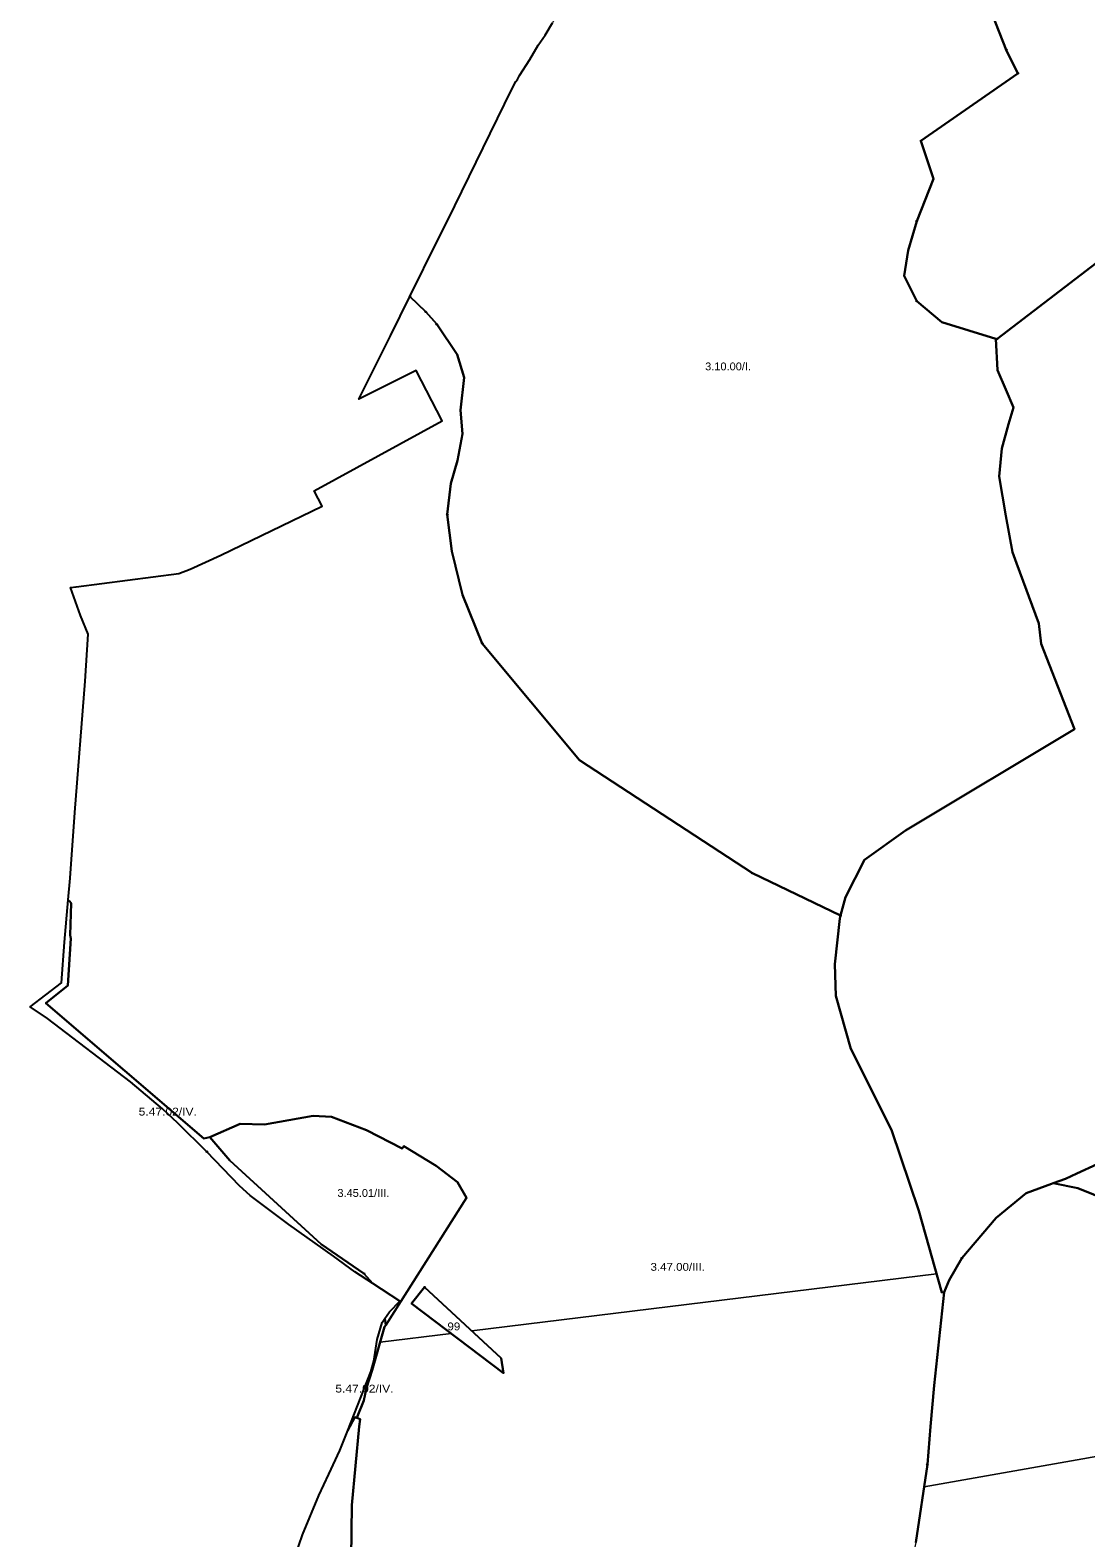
# Model space of a CAD drawing. Extents: x -650455 to -642254, y -1075222 to -1066610.
# Drawn here: x -649036 to -647687, y -1073142 to -1071216 of the extents above; entities that cross this region are included whole.
import ezdxf
from ezdxf.enums import TextEntityAlignment as Align

# ---------------------------------------------------------------- set-up
doc = ezdxf.new("R2010")
doc.units = 0
doc.header["$LTSCALE"] = 4
doc.header["$PDMODE"] = 32
doc.header["$PDSIZE"] = 2
for name, color, linetype, lineweight in [('1', 7, 'Continuous', 25), ('11', 7, 'Continuous', 13), ('12', 7, 'Continuous', 13), ('13', 7, 'Continuous', 13), ('14', 7, 'Continuous', 13), ('16', 7, 'Continuous', 13)]:
    doc.layers.add(name, color=color, linetype=linetype, lineweight=lineweight)
doc.layers.add('2', color=7, linetype='Continuous')

msp = doc.modelspace()

# ---------------------------------------------------------------- linework, layer by layer
at = {"layer": '1'}
for points in [[(-647994, -1072324), (-648000.504, -1072347.414), (-648113.117, -1072293.193), (-648334.004, -1072148.767), (-648458.304, -1071999.711), (-648483.733, -1071937.503), (-648497.128, -1071881.651), (-648503.031, -1071835.108), (-648498.263, -1071795.376), (-648489.863, -1071765.861), (-648483.733, -1071731.805), (-648486, -1071701.501), (-648481.5, -1071660), (-648490.5, -1071630.501), (-648516.5, -1071592), (-648530.5, -1071576.001), (-648550.69, -1071556.284), (-648515.528, -1071484.719), (-648502.316, -1071458.869), (-648421.035, -1071292.285), (-648415.434, -1071281.946), (-648413.28, -1071279.36), (-648410.551, -1071274.192), (-648397.483, -1071253.511), (-648386.713, -1071235.418), (-648378.097, -1071222.492), (-648368.619, -1071206.983)], [(-647806.937, -1071195.687), (-647788.736, -1071241.189), (-647773.924, -1071271.486), (-647897.806, -1071357.665), (-647881.648, -1071406.14), (-647903.192, -1071460.002), (-647913.965, -1071497.705), (-647919.351, -1071530.022), (-647903.192, -1071562.339), (-647870.875, -1071589.27), (-647801.949, -1071610.478), (-647799.782, -1071650.366), (-647789.455, -1071675.321), (-647779.56, -1071698.124), (-647786.013, -1071719.637), (-647794.619, -1071750.616), (-647797.63, -1071786.328), (-647789.455, -1071836.453), (-647780.85, -1071882.921), (-647775.687, -1071897.12), (-647747.29, -1071974.351), (-647744.278, -1072000.167), (-647701.628, -1072109.378), (-647917.5, -1072238.5), (-647970, -1072276), (-647994, -1072324)], [(-647412.981, -1071489.088), (-647446.149, -1071408.082), (-647470.706, -1071328.032), (-647494.813, -1071270.777), (-647498.258, -1071279.39), (-647499.23, -1071276.872), (-647515.389, -1071314.575), (-647547.706, -1071336.12), (-647526.161, -1071400.754), (-647800.855, -1071610.814), (-647801.949, -1071610.478), (-647870.875, -1071589.27), (-647903.192, -1071562.339), (-647919.351, -1071530.022), (-647913.965, -1071497.705), (-647903.192, -1071460.002), (-647881.648, -1071406.14), (-647897.806, -1071357.665), (-647773.924, -1071271.486), (-647788.736, -1071241.189), (-647806.937, -1071195.687)], [(-647672.5, -1072665), (-647698.521, -1072676.851), (-647713.137, -1072683.505), (-647728.952, -1072689.256), (-647731, -1072690.001), (-647763.5, -1072702.001), (-647801.5, -1072733.5), (-647845.5, -1072785), (-647861.5, -1072813), (-647868, -1072828.501), (-647871, -1072829.001), (-647900.5, -1072724.5), (-647935.5, -1072621.001), (-647987.5, -1072517.5), (-648006.5, -1072450), (-648008, -1072409.5), (-648001.5, -1072351.001), (-648000.504, -1072347.414), (-647994, -1072324), (-647970, -1072276), (-647917.5, -1072238.5), (-647701.628, -1072109.378), (-647744.278, -1072000.167), (-647747.29, -1071974.351), (-647775.687, -1071897.12), (-647780.85, -1071882.921), (-647789.455, -1071836.453), (-647797.63, -1071786.328), (-647794.619, -1071750.616), (-647786.013, -1071719.637), (-647779.56, -1071698.124), (-647789.455, -1071675.321), (-647799.782, -1071650.366), (-647801.949, -1071610.478), (-647800.855, -1071610.814), (-647526.161, -1071400.754)], [(-648845.916, -1071910.237), (-648831.479, -1071904.954), (-648792.396, -1071886.988), (-648662.822, -1071824.472), (-648673.033, -1071804.745), (-648509.304, -1071715.273), (-648542.754, -1071651.164), (-648615.992, -1071687.445), (-648575.5, -1071606.779), (-648550.69, -1071556.284), (-648530.5, -1071576.001), (-648516.5, -1071592), (-648490.5, -1071630.501)], [(-648490.5, -1071630.501), (-648481.5, -1071660), (-648486, -1071701.501), (-648483.733, -1071731.805), (-648489.863, -1071765.861), (-648498.263, -1071795.376), (-648503.031, -1071835.108), (-648497.128, -1071881.651), (-648483.733, -1071937.503), (-648458.304, -1071999.711), (-648334.004, -1072148.767), (-648113.117, -1072293.193), (-648000.504, -1072347.414), (-648001.5, -1072351.001), (-648008, -1072409.5), (-648006.5, -1072450), (-647987.5, -1072517.5), (-647935.5, -1072621.001), (-647900.5, -1072724.5), (-647871, -1072829.001), (-647868, -1072828.501), (-647881, -1072947.5), (-647885.418, -1073000), (-647889.5, -1073048.5), (-647904.5, -1073148.001)], [(-648626.5, -1073235.5), (-648625, -1073100.5), (-648615.407, -1073000), (-648614.5, -1072990.501), (-648618.5, -1072989), (-648609.5, -1072967), (-648606, -1072950.5), (-648599, -1072928), (-648583, -1072872.501), (-648581.642, -1072870.363), (-648478.5, -1072708), (-648490, -1072688), (-648517, -1072667.001), (-648558.691, -1072641.986), (-648560.5, -1072645.001), (-648606, -1072621.501), (-648651, -1072604.501), (-648674.5, -1072603), (-648736.5, -1072614.001), (-648767.5, -1072613.501), (-648806.5, -1072630.501), (-648814, -1072632), (-649016, -1072459.001), (-648988, -1072436.5), (-648984, -1072376.5), (-648985, -1072372.5), (-648983.5, -1072331.5), (-648985.611, -1072329.098), (-648987.292, -1072327.185), (-648984.907, -1072299.389), (-648978.921, -1072215.554), (-648965.541, -1072047.881), (-648961.667, -1071987.999), (-648971.526, -1071964.046), (-648984.389, -1071928.3), (-648977.161, -1071927.325), (-648845.916, -1071910.237)], [(-647639.5, -1072719.001), (-647697.5, -1072695.5), (-647728.952, -1072689.256), (-647713.137, -1072683.505), (-647698.521, -1072676.851), (-647672.5, -1072665), (-647660, -1072659.5), (-647610, -1072633.501), (-647571.5, -1072606.001), (-647536, -1072573.001), (-647511.5, -1072543), (-647500, -1072504.667), (-647498, -1072498), (-647495, -1072475.501), (-647474.5, -1072442.501), (-647439.5, -1072402.001), (-647391, -1072357), (-647361, -1072335.5), (-647349, -1072333), (-647336.5, -1072335.5), (-647316, -1072351.5), (-647308, -1072361.501)], [(-647904.5, -1073148.001), (-647889.5, -1073048.5), (-647885.418, -1073000), (-647881, -1072947.5), (-647868, -1072828.501), (-647861.5, -1072813), (-647845.5, -1072785), (-647801.5, -1072733.5), (-647763.5, -1072702.001), (-647731, -1072690.001), (-647728.952, -1072689.256), (-647697.5, -1072695.5), (-647639.5, -1072719.001), (-647587, -1072756.001), (-647543, -1072805.5), (-647522, -1072821.5), (-647515.5, -1072825), (-647500, -1072834.548), (-647453, -1072863.5), (-647421.34, -1072872.531), (-647410, -1072877.001), (-647339.5, -1072889.001)], [(-648697.333, -1073165.774), (-648687.999, -1073138.202), (-648667.032, -1073088.227), (-648654.486, -1073060.948), (-648640.322, -1073030.783), (-648630.2, -1073005.113), (-648627.452, -1073000), (-648621, -1072988), (-648618.5, -1072989), (-648614.5, -1072990.501), (-648615.407, -1073000), (-648625, -1073100.5), (-648626.5, -1073235.5)]]:
    msp.add_lwpolyline(points, dxfattribs=at)
for points in [[(-649016, -1072459.001), (-648814, -1072632), (-648806.5, -1072630.501), (-648781, -1072660), (-648664, -1072767.001), (-648609.5, -1072804.501), (-648598.112, -1072817.407), (-648620.935, -1072802.594), (-648648.364, -1072782.202), (-648705.519, -1072741.992), (-648754.776, -1072704.94), (-648768.275, -1072692.734), (-648810.208, -1072648.934), (-648847.402, -1072612.314), (-648866.789, -1072594.363), (-648907.86, -1072559.755), (-649013.849, -1072478.813), (-649035.963, -1072463.892), (-648995.823, -1072433.245), (-648991.95, -1072381.465), (-648987.292, -1072327.185), (-648985.611, -1072329.098), (-648983.5, -1072331.5), (-648985, -1072372.5), (-648984, -1072376.5), (-648988, -1072436.5)], [(-648581.642, -1072870.363), (-648582.835, -1072862.192), (-648576.781, -1072853.444), (-648563.753, -1072839.708), (-648598.112, -1072817.407), (-648609.5, -1072804.501), (-648664, -1072767.001), (-648781, -1072660), (-648806.5, -1072630.501), (-648767.5, -1072613.501), (-648736.5, -1072614.001), (-648674.5, -1072603), (-648651, -1072604.501), (-648606, -1072621.501), (-648560.5, -1072645.001), (-648558.691, -1072641.986), (-648517, -1072667.001), (-648490, -1072688), (-648478.5, -1072708)], [(-648434, -1072912.501), (-648431, -1072932), (-648548.5, -1072843), (-648532, -1072822)], [(-648548.5, -1072843), (-648431, -1072932), (-648434, -1072912.501), (-648532, -1072822)], [(-648609.5, -1072967), (-648618.5, -1072989), (-648621, -1072988), (-648627.452, -1073000), (-648630.2, -1073005.113), (-648600.686, -1072930.26), (-648596.665, -1072916.474), (-648592.501, -1072888.9), (-648586.288, -1072867.182), (-648582.835, -1072862.192), (-648581.642, -1072870.363), (-648583, -1072872.501), (-648599, -1072928), (-648606, -1072950.5)]]:
    msp.add_lwpolyline(points, close=True, dxfattribs=at)
at = {"layer": '11'}
msp.add_line((-647788.736, -1071241.189), (-647806.937, -1071195.687), dxfattribs=at)
for points in [[(-648327.713, -1071139.525), (-648367.47, -1071204.399), (-648368.619, -1071206.983), (-648378.097, -1071222.492), (-648386.713, -1071235.418), (-648397.483, -1071253.511), (-648410.551, -1071274.192), (-648413.28, -1071279.36), (-648415.434, -1071281.946), (-648421.035, -1071292.285), (-648502.316, -1071458.869), (-648515.528, -1071484.719), (-648550.69, -1071556.284)], [(-647897.806, -1071357.665), (-647773.924, -1071271.486), (-647788.736, -1071241.189)], [(-647903.192, -1071460.002), (-647881.648, -1071406.14), (-647897.806, -1071357.665)], [(-647526.161, -1071400.754), (-647800.855, -1071610.814), (-647801.949, -1071610.478), (-647799.782, -1071650.366), (-647789.455, -1071675.321), (-647779.56, -1071698.124), (-647786.013, -1071719.637), (-647794.619, -1071750.616), (-647797.63, -1071786.328), (-647789.455, -1071836.453), (-647780.85, -1071882.921), (-647775.687, -1071897.12), (-647747.29, -1071974.351), (-647744.278, -1072000.167), (-647701.628, -1072109.378), (-647917.5, -1072238.5), (-647970, -1072276), (-647994, -1072324), (-648000.504, -1072347.414)], [(-647903.192, -1071562.339), (-647919.351, -1071530.022), (-647913.965, -1071497.705), (-647903.192, -1071460.002)], [(-648550.69, -1071556.284), (-648530.5, -1071576.001), (-648516.5, -1071592)], [(-648334.004, -1072148.767), (-648113.117, -1072293.193), (-648000.504, -1072347.414), (-647994, -1072324), (-647970, -1072276), (-647917.5, -1072238.5), (-647701.628, -1072109.378), (-647744.278, -1072000.167), (-647747.29, -1071974.351), (-647775.687, -1071897.12), (-647780.85, -1071882.921), (-647789.455, -1071836.453), (-647797.63, -1071786.328), (-647794.619, -1071750.616), (-647786.013, -1071719.637), (-647779.56, -1071698.124), (-647789.455, -1071675.321), (-647799.782, -1071650.366), (-647801.949, -1071610.478), (-647870.875, -1071589.27), (-647903.192, -1071562.339)], [(-648516.5, -1071592), (-648490.5, -1071630.501), (-648481.5, -1071660), (-648486, -1071701.501), (-648483.733, -1071731.805), (-648489.863, -1071765.861), (-648498.263, -1071795.376), (-648503.031, -1071835.108)], [(-648503.031, -1071835.108), (-648497.128, -1071881.651), (-648483.733, -1071937.503), (-648458.304, -1071999.711), (-648334.004, -1072148.767)], [(-648000.504, -1072347.414), (-648001.5, -1072351.001), (-648008, -1072409.5), (-648006.5, -1072450), (-647987.5, -1072517.5), (-647935.5, -1072621.001), (-647900.5, -1072724.5), (-647871, -1072829.001), (-647868, -1072828.501), (-647861.5, -1072813), (-647845.5, -1072785)], [(-647845.5, -1072785), (-647801.5, -1072733.5), (-647763.5, -1072702.001), (-647731, -1072690.001), (-647728.952, -1072689.256), (-647713.137, -1072683.505), (-647698.521, -1072676.851), (-647672.5, -1072665), (-647660, -1072659.5), (-647610, -1072633.501), (-647571.5, -1072606.001), (-647536, -1072573.001), (-647511.5, -1072543), (-647500, -1072504.667), (-647498, -1072498), (-647495, -1072475.501), (-647474.5, -1072442.501), (-647439.5, -1072402.001), (-647391, -1072357), (-647361, -1072335.5), (-647349, -1072333), (-647336.5, -1072335.5), (-647316, -1072351.5), (-647308, -1072361.501)], [(-647421.34, -1072872.531), (-647453, -1072863.5), (-647500, -1072834.548), (-647515.5, -1072825), (-647522, -1072821.5), (-647543, -1072805.5), (-647587, -1072756.001), (-647639.5, -1072719.001), (-647697.5, -1072695.5), (-647728.952, -1072689.256), (-647731, -1072690.001), (-647763.5, -1072702.001), (-647801.5, -1072733.5), (-647845.5, -1072785), (-647861.5, -1072813), (-647868, -1072828.501), (-647881, -1072947.5), (-647885.418, -1073000), (-647889.5, -1073048.5)], [(-647339.5, -1072889.001), (-647407.174, -1072877.482), (-647467.805, -1073000), (-647452.469, -1073000), (-647459.21, -1073004.071), (-647476.435, -1073003.416), (-647893.795, -1073076.991), (-647904.5, -1073148.001), (-647917.5, -1073209.501), (-647919.5, -1073256), (-647914.5, -1073287.5), (-647902, -1073313.501), (-647885, -1073332.5), (-647865, -1073347.001), (-647852.5, -1073352.5), (-647735.5, -1073384), (-647648, -1073415.501), (-647589.5, -1073433)], [(-647889.5, -1073048.5), (-647893.795, -1073076.991), (-647476.435, -1073003.416)]]:
    msp.add_lwpolyline(points, dxfattribs=at)
for p in [(-647788.736, -1071241.189), (-647897.806, -1071357.665), (-647903.192, -1071460.002), (-648550.69, -1071556.284), (-647903.192, -1071562.339), (-648516.5, -1071592), (-648503.031, -1071835.108), (-648000.504, -1072347.414), (-647845.5, -1072785), (-647889.5, -1073048.5)]:
    msp.add_point(p, dxfattribs=at)
at = {"layer": '12'}
for points in [[(-648110.225, -1071019.369), (-647998.802, -1070960.38), (-647920.15, -1070914.5), (-647887.378, -1070888.282), (-647867.716, -1070875.174), (-647858.53, -1070886.459), (-647842.598, -1070939.564), (-647837.212, -1071004.198), (-647821.053, -1071058.06), (-647804.895, -1071111.921), (-647810.281, -1071160.397), (-647810.281, -1071187.327), (-647806.937, -1071195.687), (-647788.736, -1071241.189), (-647773.924, -1071271.486)], [(-647773.924, -1071271.486), (-647897.806, -1071357.665), (-647881.648, -1071406.14), (-647903.192, -1071460.002), (-647913.965, -1071497.705), (-647919.351, -1071530.022), (-647903.192, -1071562.339), (-647870.875, -1071589.27), (-647801.949, -1071610.478), (-647800.855, -1071610.814)], [(-647800.855, -1071610.814), (-647526.161, -1071400.754), (-647547.706, -1071336.12)]]:
    msp.add_lwpolyline(points, dxfattribs=at)
for p in [(-647773.924, -1071271.486), (-647800.855, -1071610.814)]:
    msp.add_point(p, dxfattribs=at)
at = {"layer": '13'}
msp.add_line((-648000.504, -1072347.414), (-648113.117, -1072293.193), dxfattribs=at)
for points in [[(-648530.5, -1071576.001), (-648550.69, -1071556.284), (-648575.5, -1071606.779), (-648615.992, -1071687.445), (-648542.754, -1071651.164), (-648509.304, -1071715.273), (-648673.033, -1071804.745), (-648662.822, -1071824.472), (-648792.396, -1071886.988), (-648831.479, -1071904.954), (-648845.916, -1071910.237), (-648977.161, -1071927.325), (-648984.389, -1071928.3), (-648971.526, -1071964.046), (-648961.667, -1071987.999), (-648965.541, -1072047.881), (-648978.921, -1072215.554), (-648984.907, -1072299.389), (-648987.292, -1072327.185), (-648985.611, -1072329.098), (-648983.5, -1072331.5), (-648985, -1072372.5), (-648984, -1072376.5), (-648988, -1072436.5), (-649016, -1072459.001), (-648814, -1072632), (-648806.5, -1072630.501), (-648767.5, -1072613.501), (-648736.5, -1072614.001), (-648674.5, -1072603), (-648651, -1072604.501), (-648606, -1072621.501), (-648560.5, -1072645.001), (-648558.691, -1072641.986), (-648517, -1072667.001), (-648490, -1072688), (-648478.5, -1072708), (-648581.642, -1072870.363), (-648583, -1072872.501), (-648588.72, -1072892.343)], [(-648458.304, -1071999.711), (-648483.733, -1071937.503), (-648497.128, -1071881.651), (-648503.031, -1071835.108), (-648498.263, -1071795.376), (-648489.863, -1071765.861), (-648483.733, -1071731.805), (-648486, -1071701.501), (-648481.5, -1071660), (-648490.5, -1071630.501), (-648516.5, -1071592), (-648530.5, -1071576.001)], [(-648113.117, -1072293.193), (-648334.004, -1072148.767), (-648458.304, -1071999.711)], [(-648471.444, -1072877.922), (-647877.798, -1072804.921), (-647900.5, -1072724.5), (-647935.5, -1072621.001), (-647987.5, -1072517.5), (-648006.5, -1072450), (-648008, -1072409.5), (-648001.5, -1072351.001), (-648000.504, -1072347.414)], [(-647308, -1072361.501), (-647316, -1072351.5), (-647336.5, -1072335.5), (-647349, -1072333), (-647361, -1072335.5), (-647391, -1072357), (-647439.5, -1072402.001), (-647474.5, -1072442.501), (-647495, -1072475.501), (-647498, -1072498), (-647500, -1072504.667), (-647511.5, -1072543), (-647536, -1072573.001), (-647571.5, -1072606.001), (-647610, -1072633.501), (-647660, -1072659.5), (-647672.5, -1072665), (-647698.521, -1072676.851), (-647713.137, -1072683.505), (-647728.952, -1072689.256), (-647697.5, -1072695.5), (-647639.5, -1072719.001), (-647587, -1072756.001)], [(-647904.5, -1073148.001), (-647893.795, -1073076.991), (-647889.5, -1073048.5), (-647885.418, -1073000), (-647881, -1072947.5), (-647868, -1072828.501), (-647871, -1072829.001), (-647877.798, -1072804.921), (-648471.444, -1072877.922), (-648434, -1072912.501), (-648431, -1072932), (-648498.072, -1072881.196), (-648588.72, -1072892.343), (-648599, -1072928), (-648606, -1072950.5), (-648609.5, -1072967), (-648618.5, -1072989), (-648614.5, -1072990.501), (-648615.407, -1073000), (-648625, -1073100.5), (-648626.5, -1073235.5)], [(-648588.72, -1072892.343), (-648498.072, -1072881.196), (-648548.5, -1072843), (-648532, -1072822), (-648471.444, -1072877.922)], [(-648626.5, -1073235.5), (-648625, -1073100.5), (-648615.407, -1073000), (-648614.5, -1072990.501), (-648618.5, -1072989), (-648621, -1072988), (-648627.452, -1073000), (-648630.2, -1073005.113), (-648640.322, -1073030.783), (-648654.486, -1073060.948), (-648667.032, -1073088.227), (-648687.999, -1073138.202), (-648697.333, -1073165.774)]]:
    msp.add_lwpolyline(points, dxfattribs=at)
msp.add_lwpolyline([(-648609.5, -1072804.501), (-648598.112, -1072817.407), (-648563.753, -1072839.708), (-648576.781, -1072853.444), (-648582.835, -1072862.192), (-648581.642, -1072870.363), (-648478.5, -1072708), (-648490, -1072688), (-648517, -1072667.001), (-648558.691, -1072641.986), (-648560.5, -1072645.001), (-648606, -1072621.501), (-648651, -1072604.501), (-648674.5, -1072603), (-648736.5, -1072614.001), (-648767.5, -1072613.501), (-648806.5, -1072630.501), (-648781, -1072660), (-648664, -1072767.001)], close=True, dxfattribs=at)
for p in [(-648530.5, -1071576.001), (-648458.304, -1071999.711), (-648113.117, -1072293.193), (-648000.504, -1072347.414), (-648609.5, -1072804.501)]:
    msp.add_point(p, dxfattribs=at)
at = {"layer": '14'}
for points in [[(-648810.208, -1072648.934), (-648768.275, -1072692.734), (-648754.776, -1072704.94), (-648705.519, -1072741.992), (-648648.364, -1072782.202), (-648620.935, -1072802.594), (-648598.112, -1072817.407), (-648609.5, -1072804.501), (-648664, -1072767.001), (-648781, -1072660), (-648806.5, -1072630.501), (-648814, -1072632), (-649016, -1072459.001), (-648988, -1072436.5), (-648984, -1072376.5), (-648985, -1072372.5), (-648983.5, -1072331.5), (-648985.611, -1072329.098), (-648987.292, -1072327.185), (-648991.95, -1072381.465), (-648995.823, -1072433.245), (-649035.963, -1072463.892), (-649013.849, -1072478.813), (-648907.86, -1072559.755), (-648866.789, -1072594.363), (-648847.402, -1072612.314)], [(-648630.2, -1073005.113), (-648627.452, -1073000), (-648621, -1072988), (-648618.5, -1072989), (-648609.5, -1072967), (-648606, -1072950.5), (-648599, -1072928), (-648598.992, -1072927.973), (-648588.72, -1072892.343), (-648583, -1072872.501), (-648581.642, -1072870.363), (-648582.835, -1072862.192), (-648586.288, -1072867.182), (-648592.501, -1072888.9), (-648596.665, -1072916.474), (-648600.686, -1072930.26)]]:
    msp.add_lwpolyline(points, close=True, dxfattribs=at)
msp.add_point((-648810.208, -1072648.934), dxfattribs=at)
at = {"layer": '16'}
for points in [[(-648532, -1072822), (-648548.5, -1072843), (-648431, -1072932)], [(-648431, -1072932), (-648434, -1072912.501), (-648471.444, -1072877.922), (-648532, -1072822)]]:
    msp.add_lwpolyline(points, dxfattribs=at)
msp.add_point((-648532, -1072822), dxfattribs=at)

# ---------------------------------------------------------------- texts
at = {"layer": '2'}
for s, width, p in [('3.10.00/I.', 1.05, (-648144.21, -1071650.733)), ('5.47.02/IV.', 1.15, (-648860.112, -1072602.781)), ('3.45.01/III.', 1.05, (-648610.155, -1072706.687)), ('3.47.00/III.', 1.1, (-648208.521, -1072801.06)), ('99', 1.1, (-648494.584, -1072877.117)), ('5.47.02/IV.', 1.15, (-648608.822, -1072956.603))]:
    msp.add_text(s, height=10, dxfattribs=dict(at, width=width)).set_placement(p, align=Align.CENTER)

doc.saveas('drawing.dxf')
